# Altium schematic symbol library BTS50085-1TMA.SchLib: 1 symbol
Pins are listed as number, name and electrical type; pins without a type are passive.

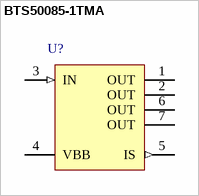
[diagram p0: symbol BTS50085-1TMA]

## BTS50085-1TMA
designator U?
Smart Highside High Current Power Switch, 1 Channel, 11.1 A Load Current, -40 to 150 degC, PG-TO220-7-4, Reel, Green; Manufacturer: Infineon; PartNumber: BTS50085-1TMA; Channels: 1; Green: TRUE; Group: Automotive Qualified; Load Current (typ): 11.1 A; Ptot (max): 170 W; Recommended Operating Voltage Max.: 58 V; Recommended Operating Voltage Min.: 5.5 V; RON @ 25degreesC: 9 mOhm; RON(max) @ 150degreesC: 17 mOhm; toff (max): 110 us; ton (max): 400 us
footprint INF-PG-TO220-7-4_N (DPAK, 7-Leads, Body 10x9.25mm, Pitch 1.27mm, IPC Medium Density)
footprint INF-PG-TO220-7-4_L (DPAK, 7-Leads, Body 10x9.25mm, Pitch 1.27mm, IPC High Density)
footprint INF-PG-TO220-7-4_M (DPAK, 7-Leads, Body 10x9.25mm, Pitch 1.27mm, IPC Low Density)
pins: 1 OUT (power) "Output to the load. The pins1,2,6 and 7 must be shorted with each other especially in high current applications!", 2 OUT (power) "Output to the load. The pins1,2,6 and 7 must be shorted with each other especially in high current applications!", 3 IN (in) "Input, activates the power switch in case of short to ground", 4 VBB (power) "Positive power supply voltage, the tab is electrically connected to this pin. In high current applications the tab should be used for the Vbb connection instead of this pin", 5 IS (out) "Diagnostic feedback providing a sense current proportional to the load current; zero current on failure (see Truth Table on page 7)", 6 OUT (power) "Output to the load. The pins1,2,6 and 7 must be shorted with each other especially in high current applications!", 7 OUT (power) "Output to the load. The pins1,2,6 and 7 must be shorted with each other especially in high current applications!"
